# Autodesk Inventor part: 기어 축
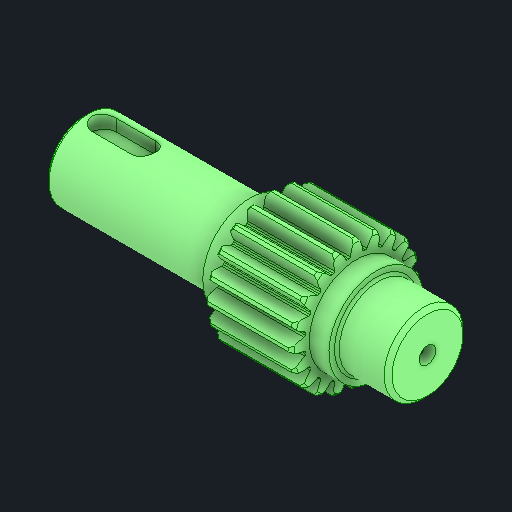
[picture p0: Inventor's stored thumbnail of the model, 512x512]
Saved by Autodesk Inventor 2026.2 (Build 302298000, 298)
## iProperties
Created: 2025-11
Part Number: 기어 축
Material: 강철, 합금
Document SubType Name: Modeling
Designer: PC2-07
Density: 7.73 g/cm^3
Appearance: 기본값
Author: jhkim
Sending System: Autodesk Inventor 2026
Preprocessor: ST-DEVELOPER v20.1
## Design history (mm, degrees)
feature "솔리드1"
node "솔리드2"
